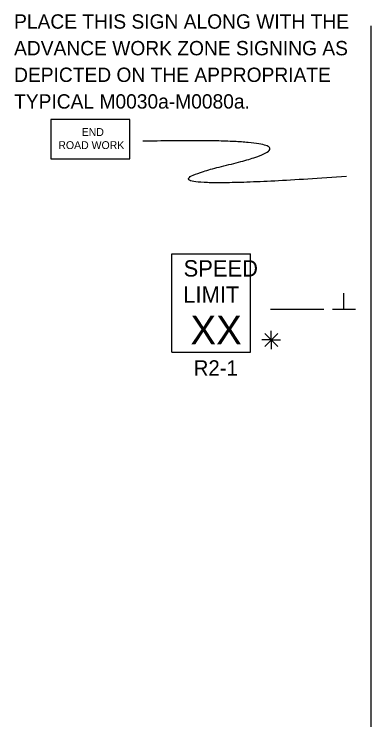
# Model space of a CAD drawing. Extents: x 16727 to 18475, y 5729 to 6909.
# Drawn here: x 16727.3 to 16901.2, y 6552.5 to 6896.9 of the extents above; entities that cross this region are included whole.
import ezdxf

# ---------------------------------------------------------------- set-up
doc = ezdxf.new("R2010")
doc.units = 0
for name, color, linetype in [('PAVT_EDGE_EX', 7, 'Continuous'), ('TRAFFIC_SIGNS_PR', 7, 'Continuous'), ('TYPICAL_TEXT_DIMEN_PR', 7, 'Continuous')]:
    doc.layers.add(name, color=color, linetype=linetype)

msp = doc.modelspace()

# ---------------------------------------------------------------- linework, layer by layer
at = {"layer": 'PAVT_EDGE_EX'}
msp.add_line((16901.23, 6891.16), (16901.23, 6061.98), dxfattribs=at)
at = {"layer": 'TRAFFIC_SIGNS_PR'}
for p, q in [((16804.14, 6779.97), (16842.54, 6779.97)), ((16804.14, 6731.97), (16804.14, 6779.97)), ((16842.54, 6731.97), (16842.54, 6779.97)), ((16804.14, 6731.97), (16842.54, 6731.97))]:
    msp.add_line(p, q, dxfattribs=at)
msp.add_lwpolyline([(16745.23, 6826.31), (16783.63, 6826.31), (16783.63, 6845.51), (16745.23, 6845.51)], close=True, dxfattribs=at)
msp.add_open_spline([(16889.36, 6817.66), (16774.14, 6809.43), (16888.05, 6837.01), (16790.1, 6834.84)], degree=2, dxfattribs=at)
at = {"layer": 'TYPICAL_TEXT_DIMEN_PR'}
for p, q in [((16888.1, 6752.97), (16888.1, 6760.76)), ((16852.23, 6752.97), (16878.23, 6752.97)), ((16882.48, 6752.97), (16893.73, 6752.97)), ((16855.84, 6741.1), (16849.46, 6734.73)), ((16849.47, 6741.1), (16855.84, 6734.73)), ((16852.65, 6737.91), (16852.65, 6742.37)), ((16852.65, 6737.91), (16848.12, 6737.91)), ((16852.65, 6737.91), (16855.84, 6737.91)), ((16852.65, 6737.91), (16857.13, 6737.91)), ((16852.65, 6737.91), (16852.65, 6733.41))]:
    msp.add_line(p, q, dxfattribs=at)

# ---------------------------------------------------------------- texts
at = {"layer": 'TRAFFIC_SIGNS_PR'}
for s, height, p in [('PLACE THIS SIGN ALONG WITH THE', 7, (16727.26, 6889.79)), ('ADVANCE WORK ZONE SIGNING AS', 7, (16727.26, 6876.79)), ('DEPICTED ON THE APPROPRIATE', 7, (16727.26, 6863.79)), ('TYPICAL M0030a-M0080a.', 7, (16727.26, 6850.79)), ('END', 3.831, (16760.23, 6837.44)), ('ROAD WORK', 3.831, (16748.84, 6831.05)), ('SPEED', 8, (16809.91, 6768.83)), ('LIMIT', 8, (16809.75, 6756.03)), ('XX', 14.031, (16813.25, 6735.73)), ('R2-1', 7.44, (16814.82, 6720.53))]:
    msp.add_text(s, height=height, dxfattribs=at).set_placement(p)

doc.saveas('drawing.dxf')
